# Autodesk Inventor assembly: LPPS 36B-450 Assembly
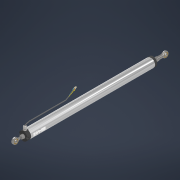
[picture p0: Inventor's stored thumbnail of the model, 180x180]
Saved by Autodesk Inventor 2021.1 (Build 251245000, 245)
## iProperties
Created: 2020-09
Part Number: LPPS 36B-450 Assembly
Document SubType Name: Assembly
Designer: J. Nielson
Author: J. Nielson
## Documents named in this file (3)
- C:\Users\Justin\Documents\CAD\The Sensor Connection\LPPS\LPPS-36B Series\3D\LPPS-36B-450\LPPS 36B-450 Assembly.iam
- C:\Users\Justin\Documents\CAD\The Sensor Connection\LPPS\LPPS-36B Series\3D\LPPS-36B-450\LPPS 36B-450 Shaft_Shrinkwrap.ipt
- C:\Users\Justin\Documents\CAD\The Sensor Connection\LPPS\LPPS-36B Series\3D\LPPS-36B-450\LPPS 36B-450_Shrinkwrap.ipt
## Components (2 placed, 2 different names)
1. LPPS 36B-450 Shaft_Shrinkwrap:1 — Mate:1, Cylindrical:1, Mate:2
2. LPPS 36B-450_Shrinkwrap:1 — Mate:1, Cylindrical:1
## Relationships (3: Mate 2, CylindricalJoint 1)
- Mate:1: LPPS 36B-450 Shaft_Shrinkwrap:1 ↔ LPPS 36B-450_Shrinkwrap:1
- Cylindrical:1: LPPS 36B-450 Shaft_Shrinkwrap:1 ↔ LPPS 36B-450_Shrinkwrap:1
- Mate:2: LPPS 36B-450 Shaft_Shrinkwrap:1
